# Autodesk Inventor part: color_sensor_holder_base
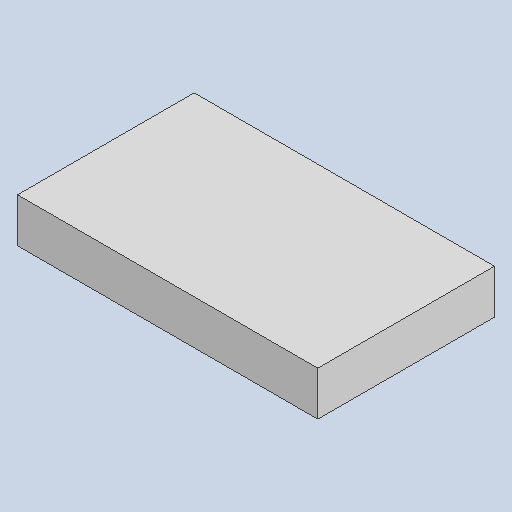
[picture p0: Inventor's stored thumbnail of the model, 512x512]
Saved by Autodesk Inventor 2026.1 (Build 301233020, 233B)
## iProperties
Created: 2026-10
Part Number: color_sensor_holder_base
Material: Generic
Document SubType Name: Modeling
Designer: alolo
Density: 1 g/cm^3
Appearance: Default
Author: alolo
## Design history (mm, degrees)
sketch "Sketch1"
  geometry: L1 (0, 0)-(34, 0); L2 (34, 0)-(34, -20); L3 (34, -20)-(0, -20); L4 (0, -20)-(0, 0)
  constraints: 8 end point, 2 parallel, 1 horizontal, 1 perpendicular
  dimensions: "d0" = 34 distance of L2.end L3.end; "d1" = 20 distance of L1.end L2.end
extrude "Extrusion1" new body sketch "Sketch1" distance "d2" = 5 (= wood_thickness); taper "d3" = 0 deg
body "Solid1"
other parameters: "slide_length" = 195 [user parameter], "slide_angle" = 7 deg [user parameter], "slide_width" = 65 [user parameter], "wood_thickness" = 5 [user parameter; used in 1 equation term], "aclyric_thickness" = 6 [user parameter]
